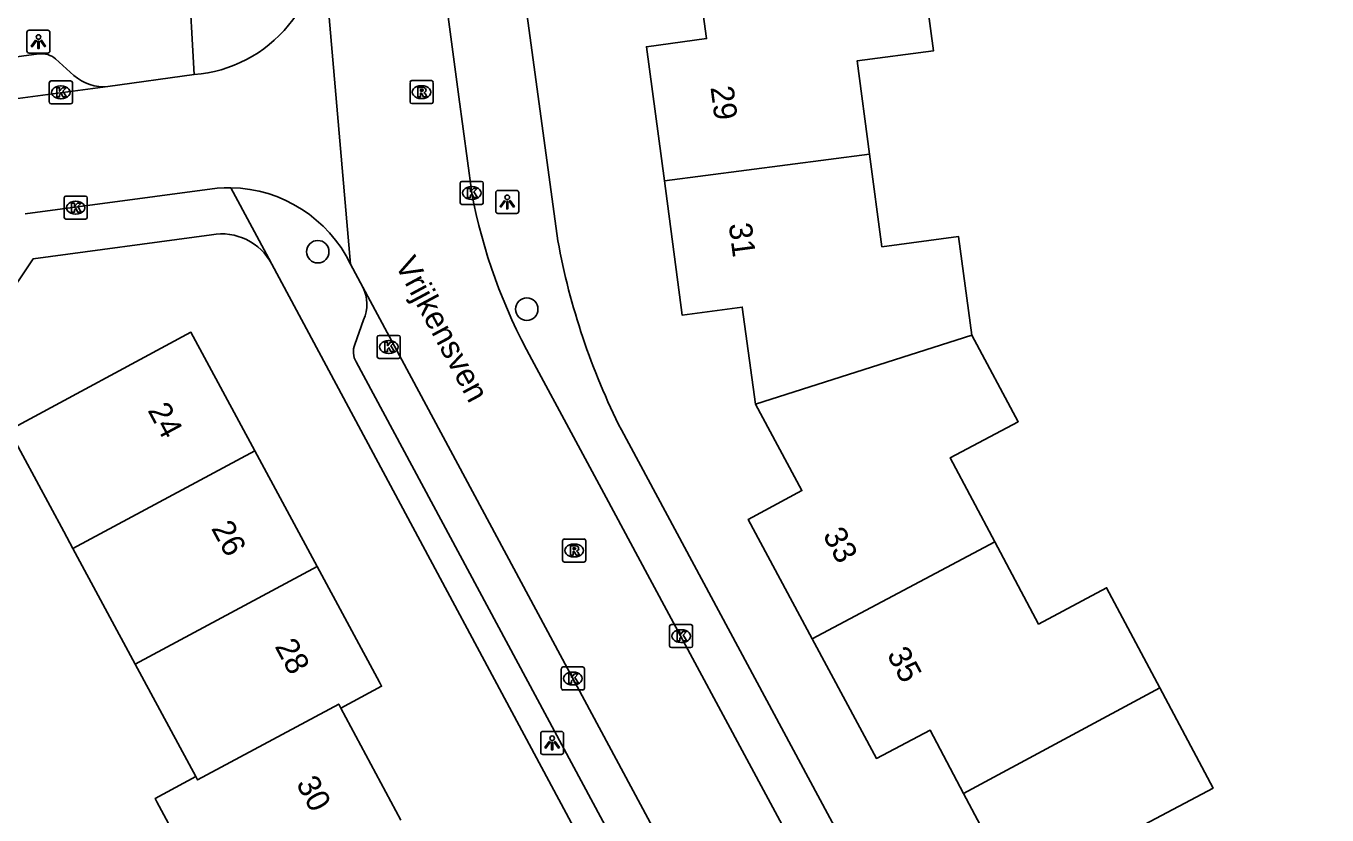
# Model space of a CAD drawing. Extents: x 163427 to 164190, y 380331 to 381641.
# Drawn here: x 163643.5 to 163700, y 381175.1 to 381209.4 of the extents above; entities that cross this region are included whole.
import ezdxf

# ---------------------------------------------------------------- set-up
doc = ezdxf.new("R2010")
doc.units = 0
for name, color, linetype in [('IMGEO_Boom', 7, 'Continuous'), ('IMGEO_Kolk', 7, 'Continuous'), ('IMGEO_Lichtpunt', 7, 'Continuous'), ('IMGEO_Openbare_ruimte_label', 7, 'Continuous'), ('IMGEO_Pand', 7, 'Continuous'), ('IMGEO_Pand_nummerreeks', 7, 'Continuous'), ('IMGEO_Rijbaan_lokaal_open', 7, 'Continuous'), ('IMGEO_Rioolput', 7, 'Continuous'), ('IMGEO_Voetpad_open', 7, 'Continuous')]:
    doc.layers.add(name, color=color, linetype=linetype)

msp = doc.modelspace()

# ---------------------------------------------------------------- linework, layer by layer
at = {"layer": 'IMGEO_Boom'}
for centre in [(163656.166, 381199.572), (163665.247, 381197.073)]:
    msp.add_circle(centre, 0.489, dxfattribs=at)
at = {"layer": 'IMGEO_Kolk'}
for p, q in [((163644.503, 381206.069), (163644.503, 381206.921)), ((163644.578, 381206.995), (163645.43, 381206.995)), ((163644.991, 381206.775), (163645.016, 381206.775)), ((163645.504, 381206.921), (163645.504, 381206.069)), ((163645.014, 381206.215), (163644.989, 381206.215)), ((163645.43, 381205.995), (163644.578, 381205.995)), ((163662.358, 381201.699), (163662.358, 381202.551)), ((163662.433, 381202.625), (163663.285, 381202.625)), ((163662.846, 381202.405), (163662.871, 381202.405)), ((163663.359, 381202.551), (163663.359, 381201.699)), ((163645.148, 381201.06), (163645.148, 381201.912)), ((163645.223, 381201.986), (163646.075, 381201.986)), ((163645.636, 381201.766), (163645.661, 381201.766)), ((163646.149, 381201.912), (163646.149, 381201.06)), ((163662.869, 381201.845), (163662.844, 381201.845)), ((163645.659, 381201.206), (163645.634, 381201.206)), ((163663.285, 381201.625), (163662.433, 381201.625)), ((163646.075, 381200.986), (163645.223, 381200.986)), ((163658.753, 381195.007), (163658.753, 381195.859)), ((163658.828, 381195.933), (163659.68, 381195.933)), ((163659.241, 381195.713), (163659.266, 381195.713)), ((163659.754, 381195.859), (163659.754, 381195.007)), ((163659.68, 381194.933), (163658.828, 381194.933)), ((163659.264, 381195.153), (163659.239, 381195.153)), ((163671.455, 381182.439), (163671.455, 381183.291)), ((163671.53, 381183.365), (163672.382, 381183.365)), ((163671.943, 381183.145), (163671.968, 381183.145)), ((163672.456, 381183.291), (163672.456, 381182.439)), ((163671.966, 381182.585), (163671.941, 381182.585)), ((163672.382, 381182.365), (163671.53, 381182.365)), ((163666.75, 381180.598), (163666.75, 381181.45)), ((163666.825, 381181.524), (163667.677, 381181.524)), ((163667.751, 381181.45), (163667.751, 381180.598)), ((163667.261, 381180.744), (163667.236, 381180.744)), ((163667.238, 381181.304), (163667.263, 381181.304)), ((163667.677, 381180.524), (163666.825, 381180.524))]:
    msp.add_line(p, q, dxfattribs=at)
for points in [[(163644.503, 381206.069), (163644.503, 381206.921)], [(163644.578, 381206.995), (163645.43, 381206.995)], [(163645.504, 381206.921), (163645.504, 381206.069)], [(163644.824, 381206.695), (163644.947, 381206.695), (163644.947, 381206.544), (163645.077, 381206.695), (163645.241, 381206.695), (163645.095, 381206.544), (163645.248, 381206.295), (163645.096, 381206.295), (163645.011, 381206.459), (163644.947, 381206.392), (163644.947, 381206.295), (163644.824, 381206.295), (163644.824, 381206.695)], [(163645.43, 381205.995), (163644.578, 381205.995)], [(163662.358, 381201.699), (163662.358, 381202.551)], [(163662.433, 381202.625), (163663.285, 381202.625)], [(163662.679, 381202.325), (163662.802, 381202.325), (163662.802, 381202.174), (163662.932, 381202.325), (163663.096, 381202.325), (163662.95, 381202.174), (163663.103, 381201.925), (163662.951, 381201.925), (163662.866, 381202.089), (163662.802, 381202.022), (163662.802, 381201.925), (163662.679, 381201.925), (163662.679, 381202.325)], [(163663.359, 381202.551), (163663.359, 381201.699)], [(163645.148, 381201.06), (163645.148, 381201.912)], [(163645.223, 381201.986), (163646.075, 381201.986)], [(163645.469, 381201.686), (163645.592, 381201.686), (163645.592, 381201.535), (163645.722, 381201.686), (163645.886, 381201.686), (163645.74, 381201.535), (163645.893, 381201.286), (163645.741, 381201.286), (163645.656, 381201.45), (163645.592, 381201.383), (163645.592, 381201.286), (163645.469, 381201.286), (163645.469, 381201.686)], [(163646.149, 381201.912), (163646.149, 381201.06)], [(163663.285, 381201.625), (163662.433, 381201.625)], [(163646.075, 381200.986), (163645.223, 381200.986)], [(163658.753, 381195.007), (163658.753, 381195.859)], [(163658.828, 381195.933), (163659.68, 381195.933)], [(163659.074, 381195.633), (163659.197, 381195.633), (163659.197, 381195.482), (163659.327, 381195.633), (163659.491, 381195.633), (163659.345, 381195.482), (163659.498, 381195.233), (163659.346, 381195.233), (163659.261, 381195.397), (163659.197, 381195.33), (163659.197, 381195.233), (163659.074, 381195.233), (163659.074, 381195.633)], [(163659.754, 381195.859), (163659.754, 381195.007)], [(163659.68, 381194.933), (163658.828, 381194.933)], [(163671.455, 381182.439), (163671.455, 381183.291)], [(163671.53, 381183.365), (163672.382, 381183.365)], [(163671.776, 381183.065), (163671.899, 381183.065), (163671.899, 381182.914), (163672.029, 381183.065), (163672.193, 381183.065), (163672.047, 381182.914), (163672.2, 381182.665), (163672.048, 381182.665), (163671.963, 381182.829), (163671.899, 381182.762), (163671.899, 381182.665), (163671.776, 381182.665), (163671.776, 381183.065)], [(163672.456, 381183.291), (163672.456, 381182.439)], [(163672.382, 381182.365), (163671.53, 381182.365)], [(163666.75, 381180.598), (163666.75, 381181.45)], [(163666.825, 381181.524), (163667.677, 381181.524)], [(163667.751, 381181.45), (163667.751, 381180.598)], [(163667.071, 381181.224), (163667.194, 381181.224), (163667.194, 381181.073), (163667.324, 381181.224), (163667.488, 381181.224), (163667.342, 381181.073), (163667.495, 381180.824), (163667.343, 381180.824), (163667.258, 381180.988), (163667.194, 381180.921), (163667.194, 381180.824), (163667.071, 381180.824), (163667.071, 381181.224)], [(163667.677, 381180.524), (163666.825, 381180.524)]]:
    msp.add_lwpolyline(points, dxfattribs=at)
for centre, start, end in [((163644.58, 381206.919), 91.552, 178.448), ((163644.58, 381206.919), 91.552, 178.448), ((163645.428, 381206.919), 1.552, 88.448), ((163645.428, 381206.919), 1.552, 88.448), ((163644.58, 381206.071), 181.552, 268.448), ((163644.58, 381206.071), 181.552, 268.448), ((163645.428, 381206.071), 271.552, 358.448), ((163645.428, 381206.071), 271.552, 358.448), ((163662.435, 381202.549), 91.552, 178.448), ((163662.435, 381202.549), 91.552, 178.448), ((163663.283, 381202.549), 1.552, 88.448), ((163663.283, 381202.549), 1.552, 88.448), ((163645.225, 381201.91), 91.552, 178.448), ((163645.225, 381201.91), 91.552, 178.448), ((163646.073, 381201.91), 1.552, 88.448), ((163646.073, 381201.91), 1.552, 88.448), ((163662.435, 381201.701), 181.552, 268.448), ((163662.435, 381201.701), 181.552, 268.448), ((163663.283, 381201.701), 271.552, 358.448), ((163663.283, 381201.701), 271.552, 358.448), ((163645.225, 381201.062), 181.552, 268.448), ((163645.225, 381201.062), 181.552, 268.448), ((163646.073, 381201.062), 271.552, 358.448), ((163646.073, 381201.062), 271.552, 358.448), ((163658.83, 381195.857), 91.552, 178.448), ((163658.83, 381195.857), 91.552, 178.448), ((163659.678, 381195.857), 1.552, 88.448), ((163659.678, 381195.857), 1.552, 88.448), ((163658.83, 381195.009), 181.552, 268.448), ((163658.83, 381195.009), 181.552, 268.448), ((163659.678, 381195.009), 271.552, 358.448), ((163659.678, 381195.009), 271.552, 358.448), ((163671.532, 381183.289), 91.552, 178.448), ((163671.532, 381183.289), 91.552, 178.448), ((163672.38, 381183.289), 1.552, 88.448), ((163672.38, 381183.289), 1.552, 88.448), ((163671.532, 381182.441), 181.552, 268.448), ((163671.532, 381182.441), 181.552, 268.448), ((163672.38, 381182.441), 271.552, 358.448), ((163672.38, 381182.441), 271.552, 358.448), ((163666.827, 381181.448), 91.552, 178.448), ((163666.827, 381181.448), 91.552, 178.448), ((163667.675, 381181.448), 1.552, 88.448), ((163667.675, 381181.448), 1.552, 88.448), ((163666.827, 381180.6), 181.552, 268.448), ((163666.827, 381180.6), 181.552, 268.448), ((163667.675, 381180.6), 271.552, 358.448), ((163667.675, 381180.6), 271.552, 358.448)]:
    msp.add_arc(centre, 0.0765, start, end, dxfattribs=at)
for centre, major_axis, ratio, start_param, end_param in [((163644.99, 381206.495), (-0.387, 0.002), 0.722429, 4.712389, 7.853982), ((163645.015, 381206.495), (-0.39, 0.002), 0.717154, 1.570796, 4.712389), ((163662.845, 381202.125), (-0.387, 0.002), 0.722429, 4.712389, 7.853982), ((163662.87, 381202.125), (-0.39, 0.002), 0.717154, 1.570796, 4.712389), ((163645.635, 381201.486), (-0.387, 0.002), 0.722429, 4.712389, 7.853982), ((163645.66, 381201.486), (-0.39, 0.002), 0.717154, 1.570796, 4.712389), ((163659.24, 381195.433), (-0.387, 0.002), 0.722429, 4.712389, 7.853982), ((163659.265, 381195.433), (-0.39, 0.002), 0.717154, 1.570796, 4.712389), ((163671.942, 381182.865), (-0.387, 0.002), 0.722429, 4.712389, 7.853982), ((163671.967, 381182.865), (-0.39, 0.002), 0.717154, 1.570796, 4.712389), ((163667.237, 381181.024), (-0.387, 0.002), 0.722429, 4.712389, 7.853982), ((163667.262, 381181.024), (-0.39, 0.002), 0.717154, 1.570796, 4.712389)]:
    msp.add_ellipse(centre, major_axis=major_axis, ratio=ratio, start_param=start_param, end_param=end_param, dxfattribs=at)
at = {"layer": 'IMGEO_Lichtpunt'}
for p, q in [((163643.533, 381209.104), (163643.533, 381208.297)), ((163643.533, 381209.104), (163643.533, 381208.297)), ((163644.435, 381209.199), (163643.627, 381209.199)), ((163644.435, 381209.199), (163643.627, 381209.199)), ((163644.529, 381208.297), (163644.529, 381209.104)), ((163644.529, 381208.297), (163644.529, 381209.104)), ((163643.627, 381208.203), (163644.435, 381208.203)), ((163643.627, 381208.203), (163644.435, 381208.203)), ((163664.803, 381202.233), (163663.995, 381202.233)), ((163664.803, 381202.233), (163663.995, 381202.233)), ((163663.901, 381202.138), (163663.901, 381201.331)), ((163663.901, 381202.138), (163663.901, 381201.331)), ((163664.897, 381201.331), (163664.897, 381202.138)), ((163664.897, 381201.331), (163664.897, 381202.138)), ((163663.995, 381201.237), (163664.803, 381201.237)), ((163663.995, 381201.237), (163664.803, 381201.237)), ((163665.853, 381178.628), (163665.853, 381177.821)), ((163665.853, 381178.628), (163665.853, 381177.821)), ((163666.755, 381178.723), (163665.947, 381178.723)), ((163666.755, 381178.723), (163665.947, 381178.723)), ((163666.849, 381177.821), (163666.849, 381178.628)), ((163666.849, 381177.821), (163666.849, 381178.628)), ((163665.947, 381177.727), (163666.755, 381177.727)), ((163665.947, 381177.727), (163666.755, 381177.727))]:
    msp.add_line(p, q, dxfattribs=at)
for points in [[(163643.907, 381208.768), (163643.946, 381208.74), (163643.758, 381208.478), (163643.72, 381208.505), (163643.907, 381208.768)], [(163644.009, 381208.72), (163644.056, 381208.72), (163644.056, 381208.398), (163644.009, 381208.398), (163644.009, 381208.72)], [(163644.119, 381208.74), (163644.157, 381208.767), (163644.344, 381208.505), (163644.305, 381208.477), (163644.119, 381208.74)], [(163664.275, 381201.802), (163664.314, 381201.774), (163664.126, 381201.512), (163664.088, 381201.539), (163664.275, 381201.802)], [(163664.377, 381201.754), (163664.424, 381201.754), (163664.424, 381201.432), (163664.377, 381201.432), (163664.377, 381201.754)], [(163664.487, 381201.774), (163664.525, 381201.801), (163664.712, 381201.539), (163664.673, 381201.511), (163664.487, 381201.774)], [(163666.227, 381178.292), (163666.266, 381178.264), (163666.078, 381178.002), (163666.04, 381178.029), (163666.227, 381178.292)], [(163666.329, 381178.244), (163666.376, 381178.244), (163666.376, 381177.922), (163666.329, 381177.922), (163666.329, 381178.244)], [(163666.439, 381178.264), (163666.477, 381178.291), (163666.664, 381178.029), (163666.625, 381178.001), (163666.439, 381178.264)]]:
    msp.add_lwpolyline(points, dxfattribs=at)
for centre in [(163644.032, 381208.902), (163664.4, 381201.936), (163666.352, 381178.426)]:
    msp.add_circle(centre, 0.0994, dxfattribs=at)
for centre, start, end in [((163643.627, 381209.104), 90, 180), ((163643.627, 381209.104), 90, 180), ((163644.435, 381209.104), 0, 90), ((163644.435, 381209.104), 0, 90), ((163643.627, 381208.297), 180, 270), ((163643.627, 381208.297), 180, 270), ((163644.435, 381208.297), 270, 0), ((163644.435, 381208.297), 270, 360), ((163663.995, 381202.138), 90, 180), ((163663.995, 381202.138), 90, 180), ((163664.803, 381202.138), 0, 90), ((163664.803, 381202.138), 0, 90), ((163663.995, 381201.331), 180, 270), ((163663.995, 381201.331), 180, 270), ((163664.803, 381201.331), 270, 0), ((163664.803, 381201.331), 270, 360), ((163665.947, 381178.628), 90, 180), ((163665.947, 381178.628), 90, 180), ((163666.755, 381178.628), 0, 90), ((163666.755, 381178.628), 0, 90), ((163665.947, 381177.821), 180, 270), ((163665.947, 381177.821), 180, 270), ((163666.755, 381177.821), 270, 0), ((163666.755, 381177.821), 270, 360)]:
    msp.add_arc(centre, 0.0946, start, end, dxfattribs=at)
at = {"layer": 'IMGEO_Pand'}
for points in [[(163682.273, 381213.17), (163682.924, 381208.304), (163679.598, 381207.86), (163680.14, 381203.81)], [(163671.227, 381202.645), (163670.45, 381208.482), (163673.058, 381208.834), (163672.643, 381211.918)], [(163680.14, 381203.81), (163671.227, 381202.645)], [(163680.14, 381203.81), (163680.678, 381199.79), (163684.006, 381200.235), (163684.59, 381195.94)], [(163675.187, 381192.951), (163674.61, 381197.166), (163672.003, 381196.808), (163671.227, 381202.645)], [(163645.527, 381186.679), (163645.133, 381187.411), (163642.764, 381191.813), (163650.656, 381196.072), (163653.429, 381190.921)], [(163675.187, 381192.951), (163684.59, 381195.94)], [(163684.59, 381195.94), (163686.605, 381192.183), (163683.645, 381190.608), (163685.58, 381186.97)], [(163677.655, 381182.742), (163674.869, 381187.935), (163677.205, 381189.188), (163675.187, 381192.951)], [(163653.429, 381190.921), (163645.527, 381186.679)], [(163653.429, 381190.921), (163656.138, 381185.89)], [(163685.58, 381186.97), (163677.655, 381182.742)], [(163685.58, 381186.97), (163687.484, 381183.391), (163690.443, 381184.965), (163692.753, 381180.622)], [(163648.234, 381181.648), (163645.527, 381186.679)], [(163656.138, 381185.89), (163648.234, 381181.648)], [(163656.138, 381185.89), (163658.847, 381180.859), (163658.938, 381180.69), (163657.169, 381179.738)], [(163684.229, 381176.031), (163682.774, 381178.783), (163680.441, 381177.549), (163677.655, 381182.742)], [(163650.865, 381176.759), (163648.234, 381181.648)], [(163684.229, 381176.031), (163692.753, 381180.622)], [(163692.753, 381180.622), (163695.072, 381176.263), (163692.094, 381174.678), (163694.003, 381171.092)], [(163650.865, 381176.759), (163650.942, 381176.615), (163657.077, 381179.909), (163657.169, 381179.738)], [(163657.169, 381179.738), (163659.78, 381174.874)], [(163651.88, 381170.634), (163649.173, 381175.665), (163649.097, 381175.807), (163650.865, 381176.759)], [(163686.134, 381166.868), (163683.359, 381172.048), (163685.685, 381173.278), (163684.229, 381176.031)]]:
    msp.add_lwpolyline(points, dxfattribs=at)
at = {"layer": 'IMGEO_Rijbaan_lokaal_open'}
for points in [[(163662.857, 381202.129), (163662.302, 381206.299), (163661.3, 381213.825), (163661.002, 381216.038), (163660.901, 381216.818)], [(163656.199, 381213.848), (163656.365, 381213.282), (163657.589, 381199.034)], [(163647.052, 381206.752), (163627.485, 381204.138)], [(163647.052, 381206.752), (163650.8, 381207.266)], [(163652.396, 381202.354), (163652.093, 381202.352), (163651.791, 381202.335), (163643.448, 381201.215)], [(163657.589, 381199.034), (163658.128, 381198.034)], [(163658.128, 381198.034), (163673.257, 381169.82)], [(163687.943, 381153.086), (163684.351, 381159.767), (163679.412, 381168.954), (163675.832, 381175.612), (163670.49, 381185.548), (163668.694, 381188.892), (163667.28, 381191.521), (163665.468, 381194.89)]]:
    msp.add_lwpolyline(points, dxfattribs=at)
for centre, radius, start, end in [((163650.326, 381213.16), 5.913, 274.5953, 6.6828), ((163652.275, 381196.444), 5.911, 25.9873, 88.8294), ((163686.642, 381206.618), 24.205, 190.6868, 208.9804)]:
    msp.add_arc(centre, radius, start, end, dxfattribs=at)
at = {"layer": 'IMGEO_Rioolput'}
for p, q in [((163660.176, 381206.08), (163660.176, 381206.932)), ((163660.251, 381207.006), (163661.103, 381207.006)), ((163660.664, 381206.786), (163660.689, 381206.786)), ((163661.177, 381206.932), (163661.177, 381206.08)), ((163660.687, 381206.226), (163660.662, 381206.226)), ((163661.103, 381206.006), (163660.251, 381206.006)), ((163666.807, 381186.16), (163666.807, 381187.012)), ((163666.882, 381187.086), (163667.734, 381187.086)), ((163667.808, 381187.012), (163667.808, 381186.16)), ((163667.295, 381186.866), (163667.32, 381186.866)), ((163667.734, 381186.086), (163666.882, 381186.086)), ((163667.318, 381186.306), (163667.293, 381186.306))]:
    msp.add_line(p, q, dxfattribs=at)
for points in [[(163660.176, 381206.08), (163660.176, 381206.932)], [(163660.251, 381207.006), (163661.103, 381207.006)], [(163661.177, 381206.932), (163661.177, 381206.08)], [(163660.765, 381206.704), (163660.513, 381206.706), (163660.513, 381206.306)], [(163660.513, 381206.306), (163660.637, 381206.306), (163660.637, 381206.468), (163660.648, 381206.468)], [(163660.691, 381206.625), (163660.637, 381206.625), (163660.637, 381206.544)], [(163660.637, 381206.544), (163660.689, 381206.544)], [(163660.695, 381206.439), (163660.766, 381206.306), (163660.906, 381206.306), (163660.841, 381206.432)], [(163661.103, 381206.006), (163660.251, 381206.006)], [(163666.807, 381186.16), (163666.807, 381187.012)], [(163666.882, 381187.086), (163667.734, 381187.086)], [(163667.808, 381187.012), (163667.808, 381186.16)], [(163667.396, 381186.784), (163667.144, 381186.786), (163667.144, 381186.386)], [(163667.144, 381186.386), (163667.268, 381186.386), (163667.268, 381186.548), (163667.279, 381186.548)], [(163667.322, 381186.705), (163667.268, 381186.705), (163667.268, 381186.624)], [(163667.268, 381186.624), (163667.32, 381186.624)], [(163667.326, 381186.519), (163667.397, 381186.386), (163667.537, 381186.386), (163667.472, 381186.512)], [(163667.734, 381186.086), (163666.882, 381186.086)]]:
    msp.add_lwpolyline(points, dxfattribs=at)
for centre, radius, start, end in [((163660.253, 381206.93), 0.0765, 91.552, 178.448), ((163660.253, 381206.93), 0.0765, 91.552, 178.448), ((163661.101, 381206.93), 0.0765, 1.552, 88.448), ((163661.101, 381206.93), 0.0765, 1.552, 88.448), ((163660.647, 381206.415), 0.0533, 26.0293, 88.6989), ((163660.673, 381206.733), 0.19, 274.7715, 282.9687), ((163660.697, 381206.529), 0.0964, 77.0061, 93.1865), ((163660.711, 381206.586), 0.0378, 276.6634, 79.6772), ((163660.764, 381206.594), 0.109, 350.3612, 89.416), ((163660.762, 381206.594), 0.112, 277.5842, 350.9817), ((163660.746, 381206.379), 0.108, 29.5134, 73.7905), ((163660.253, 381206.082), 0.0765, 181.552, 268.448), ((163660.253, 381206.082), 0.0765, 181.552, 268.448), ((163661.101, 381206.082), 0.0765, 271.552, 358.448), ((163661.101, 381206.082), 0.0765, 271.552, 358.448), ((163666.884, 381187.01), 0.0765, 91.552, 178.448), ((163666.884, 381187.01), 0.0765, 91.552, 178.448), ((163667.732, 381187.01), 0.0765, 1.552, 88.448), ((163667.732, 381187.01), 0.0765, 1.552, 88.448), ((163667.278, 381186.495), 0.0533, 26.0293, 88.6989), ((163667.304, 381186.813), 0.19, 274.7715, 282.9687), ((163667.328, 381186.609), 0.0964, 77.0061, 93.1865), ((163667.342, 381186.666), 0.0378, 276.6634, 79.6772), ((163667.395, 381186.674), 0.109, 350.3612, 89.416), ((163667.393, 381186.674), 0.112, 277.5842, 350.9817), ((163667.377, 381186.459), 0.108, 29.5134, 73.7905), ((163666.884, 381186.162), 0.0765, 181.552, 268.448), ((163666.884, 381186.162), 0.0765, 181.552, 268.448), ((163667.732, 381186.162), 0.0765, 271.552, 358.448), ((163667.732, 381186.162), 0.0765, 271.552, 358.448)]:
    msp.add_arc(centre, radius, start, end, dxfattribs=at)
for centre, major_axis, ratio, start_param, end_param in [((163660.663, 381206.506), (-0.387, 0.002), 0.722429, 4.712389, 7.853982), ((163660.688, 381206.506), (-0.39, 0.002), 0.717154, 1.570796, 4.712389), ((163667.294, 381186.586), (-0.387, 0.002), 0.722429, 4.712389, 7.853982), ((163667.319, 381186.586), (-0.39, 0.002), 0.717154, 1.570796, 4.712389)]:
    msp.add_ellipse(centre, major_axis=major_axis, ratio=ratio, start_param=start_param, end_param=end_param, dxfattribs=at)
at = {"layer": 'IMGEO_Voetpad_open'}
for points in [[(163655.852, 381278.964), (163659.796, 381250), (163666.598, 381200.045)], [(163650.544, 381211.665), (163650.8, 381207.266)], [(163627.248, 381205.915), (163644.043, 381208.17)], [(163644.77, 381207.948), (163645.573, 381207.235)], [(163652.396, 381202.354), (163654.146, 381199.095), (163654.176, 381199.033)], [(163651.552, 381200.311), (163643.8, 381199.258), (163642.478, 381197.292), (163630.068, 381195.629), (163628.28, 381197.194), (163625.277, 381196.79)], [(163692.121, 381128.24), (163654.176, 381199.033)], [(163657.772, 381195.544), (163658.156, 381196.608)], [(163670.557, 381171.096), (163657.829, 381194.781)], [(163669.362, 381191.825), (163689.269, 381154.766), (163691.64, 381154.139), (163699.506, 381139.528), (163698.631, 381137.07), (163700.018, 381134.477)]]:
    msp.add_lwpolyline(points, dxfattribs=at)
for centre, radius, start, end in [((163644.167, 381207.273), 0.905, 48.1894, 97.849), ((163646.854, 381208.651), 1.909, 227.865, 275.9639), ((163651.979, 381197.855), 2.493, 28.1979, 99.8659), ((163696.557, 381205.544), 30.459, 190.4011, 206.7697), ((163656.591, 381197.291), 1.708, 336.4421, 25.8077), ((163658.652, 381195.226), 0.936, 160.1458, 208.3989)]:
    msp.add_arc(centre, radius, start, end, dxfattribs=at)

# ---------------------------------------------------------------- texts
at = {"layer": 'IMGEO_Openbare_ruimte_label'}
msp.add_text('Vrijkensven', height=1, rotation=298.2309, dxfattribs=at).set_placement((163659.5, 381199.025))
at = {"layer": 'IMGEO_Pand_nummerreeks'}
for s, rotation, p in [('29', 277.5776, (163673.228, 381206.715)), ('31', 277.5776, (163674.019, 381200.766)), ('24', 298.299, (163648.757, 381192.681)), ('26', 298.299, (163651.518, 381187.553)), ('33', 298.2132, (163678.091, 381187.258)), ('28', 298.2982, (163654.279, 381182.424)), ('35', 298.2132, (163680.877, 381182.065)), ('30', 298.2294, (163655.207, 381176.457))]:
    msp.add_text(s, height=1, rotation=rotation, dxfattribs=at).set_placement(p)

doc.saveas('drawing.dxf')
